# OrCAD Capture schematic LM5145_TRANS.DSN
size E; title: LM5145 6-V to 75-V Synchronous Buck DC-DC Controller; rev: 1.0; note: Datasheet: SNVSAI4     EVM: SNVU545A; note: Synchronous Step Down Converter
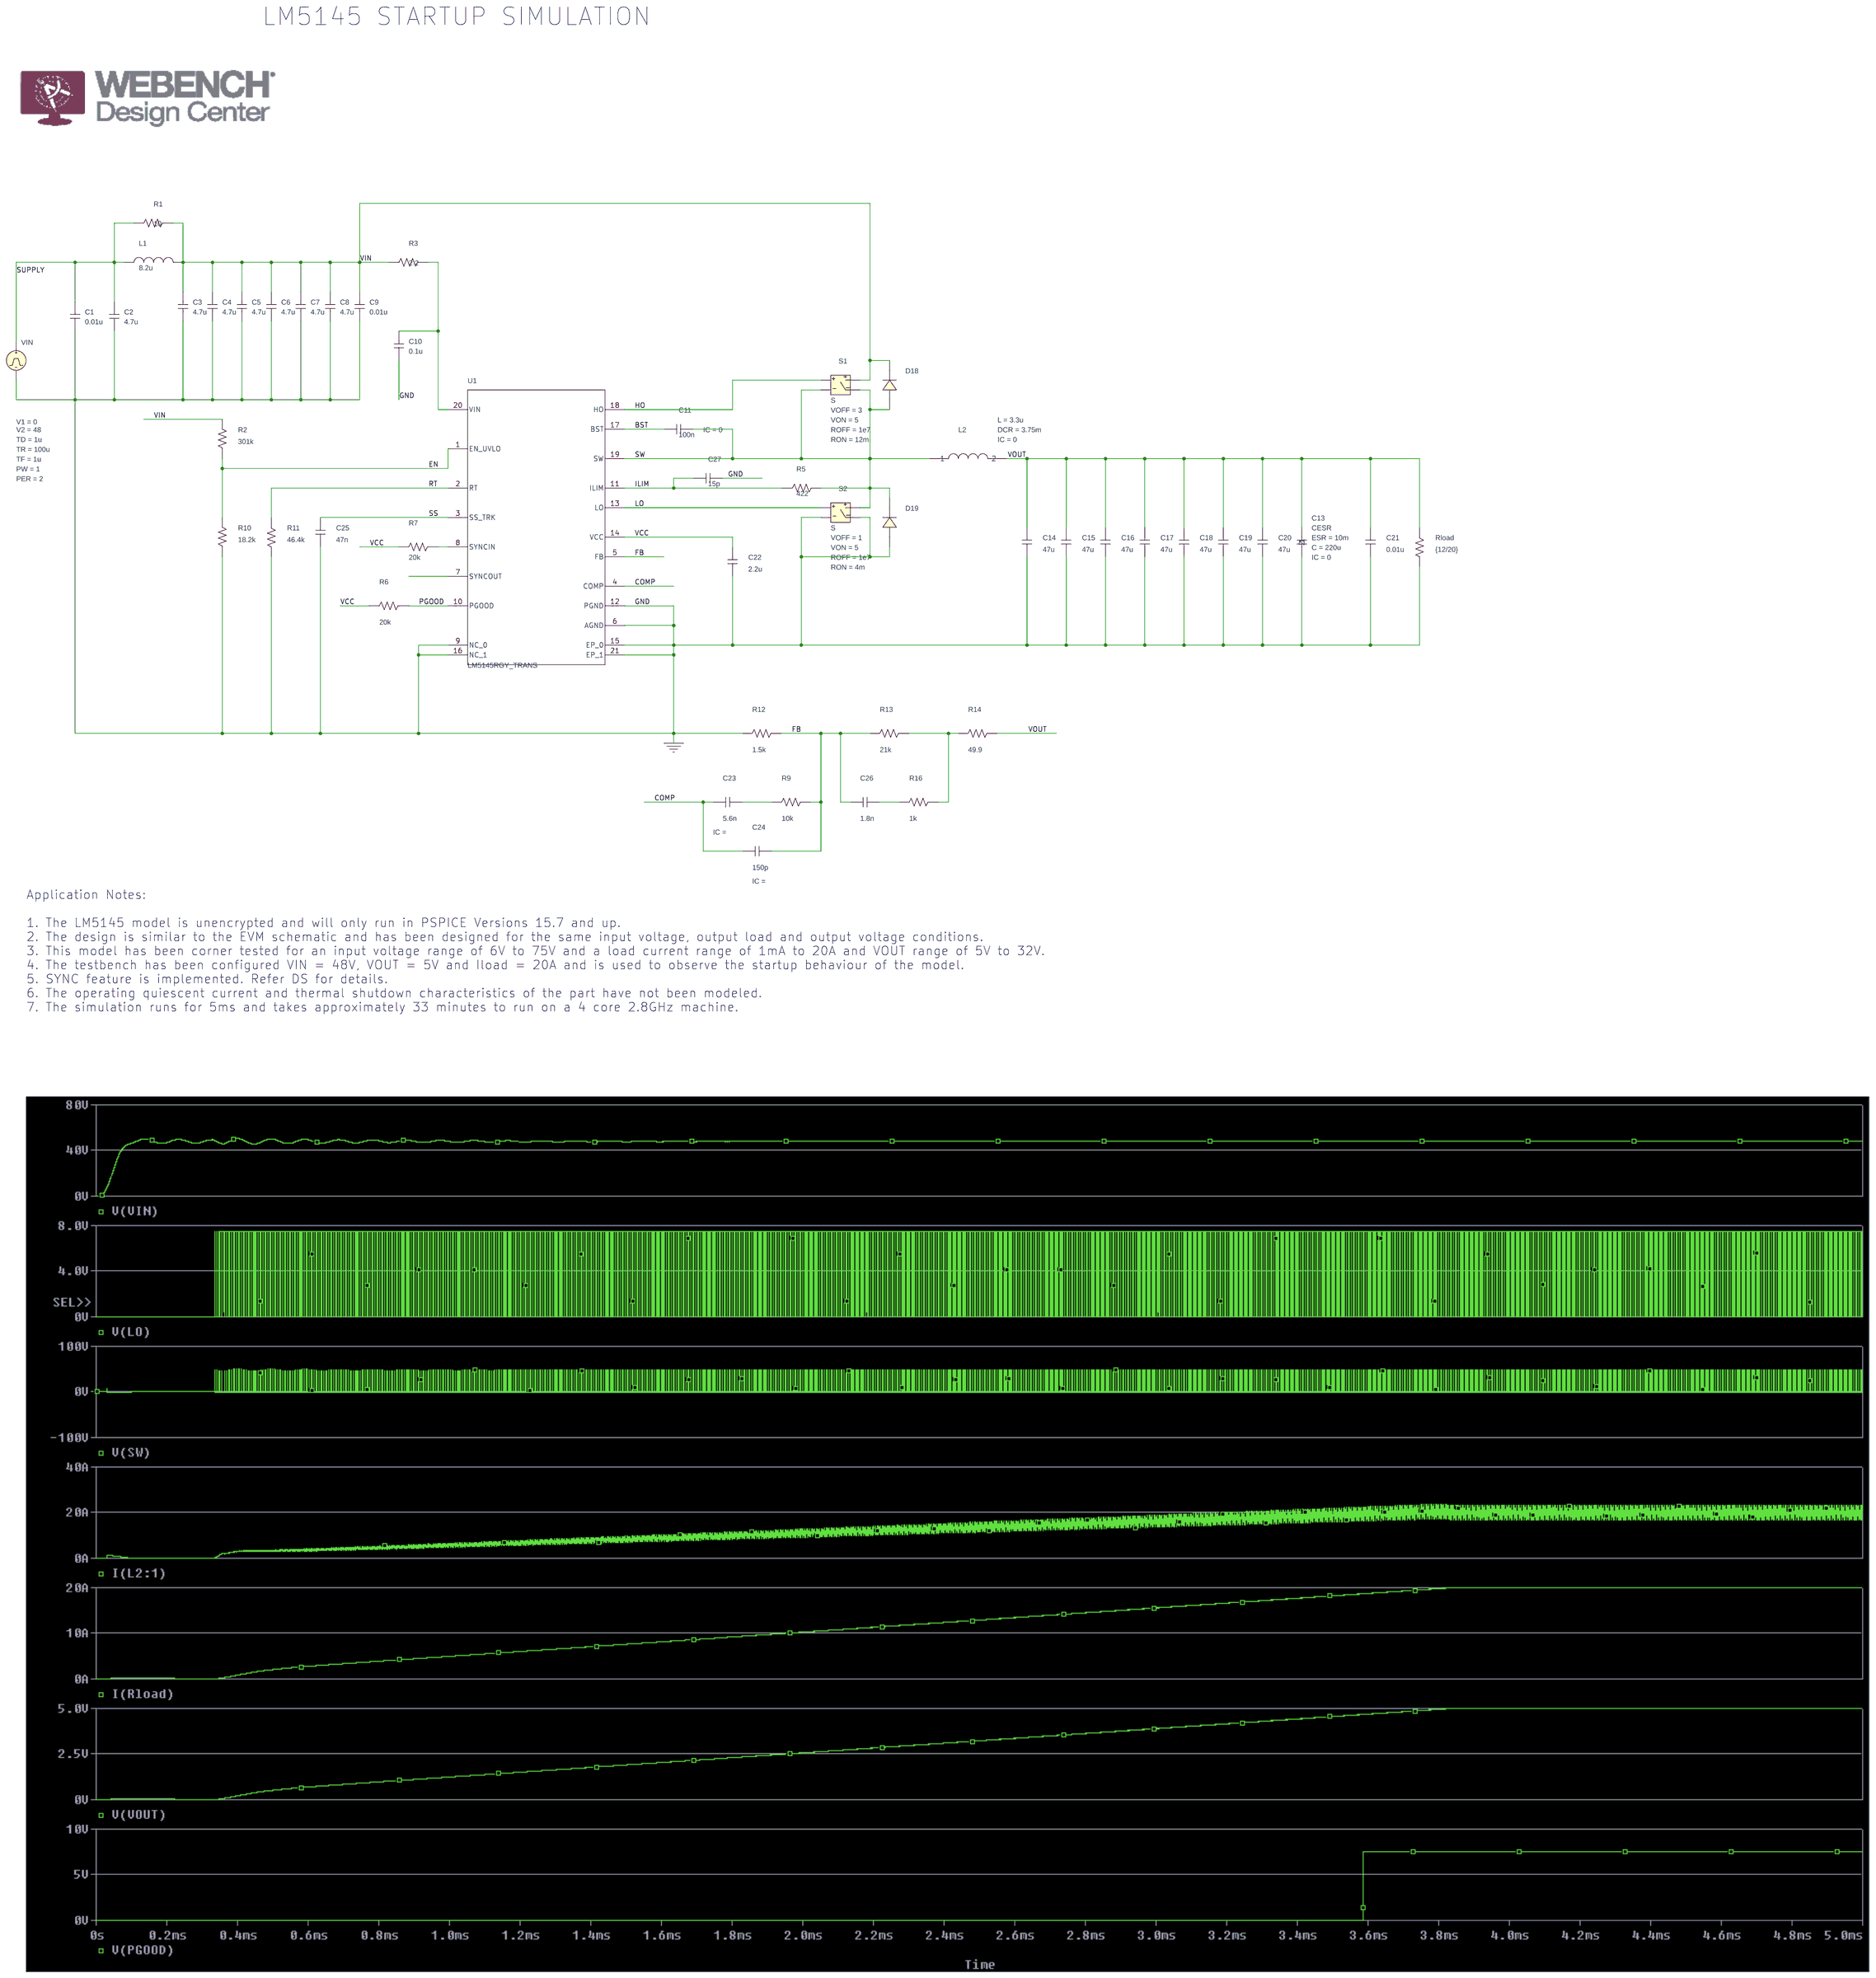
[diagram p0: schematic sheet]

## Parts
C1  0.01u  [RAD/CK05]
C2  4.7u  [RAD/CK05]
C3  4.7u  [RAD/CK05]
C4  4.7u  [RAD/CK05]
C5  4.7u  [RAD/CK05]
C6  4.7u  [RAD/CK05]
C7  4.7u  [RAD/CK05]
C8  4.7u  [RAD/CK05]
C9  0.01u  [RAD/CK05]
C10  0.1u  [RAD/CK05]
C11  100n  [RAD/CK05]
C13  CESR
C14  47u  [RAD/CK05]
C15  47u  [RAD/CK05]
C16  47u  [RAD/CK05]
C17  47u  [RAD/CK05]
C18  47u  [RAD/CK05]
C19  47u  [RAD/CK05]
C20  47u  [RAD/CK05]
C21  0.01u  [RAD/CK05]
C22  2.2u  [RAD/CK05]
C23  5.6n  [RAD/CK05]
C24  150p  [RAD/CK05]
C25  47n  [RAD/CK05]
C26  1.8n  [RAD/CK05]
C27  15p  [RAD/CK05]
D18  D_D1
D19  D_D1
L1  8.2u  [DISC/.350x.175/LS.200x.100/.034]
L2  LDCR
R1  10  [AX/RC05]
R2  301k  [AX/RC05]
R3  2.2  [AX/RC05]
R5  422  [AX/RC05]
R6  20k  [AX/RC05]
R7  20k  [AX/RC05]
R9  10k  [AX/RC05]
R10  18.2k  [AX/RC05]
R11  46.4k  [AX/RC05]
R12  1.5k  [AX/RC05]
R13  21k  [AX/RC05]
R14  49.9  [AX/RC05]
R16  1k  [AX/RC05]
Rload  {12/20}  [AX/RC05]
S1  S
S2  S
U1  LM5145RGY_TRANS  [RGY0020B]
VIN  VPULSE

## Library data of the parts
C1-C10 C14-C27 = c
C11 = c: IC: 0
C13 = CESR: C: 220u; ESR: 10m; IC: 0; PSpiceTemplate: X^@REFDES %1 %2 @MODEL PARAMS: ?C|C=@C||C=10U| ?ESR|ESR=@ESR||ESR=2M| ?IC|IC=@IC||IC=1N| ?X|X=@X||X=1|; X: 1
D18 D19 = D_D1
L1 = l
L2 = LDCR: DCR: 3.75m; IC: 0; L: 3.3u
R1 R3 R5-R7 R9 R11-R14 R16 = r
R2 R10 Rload = R
S1 = S: ROFF: 1e7; RON: 12m; VOFF: 3; VON: 5
S2 = S: ROFF: 1e7; RON: 4m; VOFF: 1; VON: 5
U1 = LM5145RGY_TRANS
VIN = VPULSE: PER: 2; PW: 1; TD: 1u; TF: 1u; TR: 100u; V1: 0; V2: 48

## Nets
VCC: C22.1 R6.2 R7.2 U1.14(VCC)
VIN: C3.1 C4.1 C5.1 C6.1 C7.1 C8.1 C9.1 D18.1(C) L1.2 R1.1 R2.2 R3.2 S1.2(3)
0: C1.2 C2.2 C3.2 C4.2 C5.2 C6.2 C7.2 C8.2 C9.2 C10.2 C13.2 C14.2 C15.2 C16.2 C17.2 C18.2 C19.2 C20.2 C21.2 C22.2 C25.2 C27.2 D19.2(A) R10.1 R11.2 R12.2 Rload.2 S2.1(2) S2.3(4) U1.6(AGND) U1.9(NC_0) U1.12(PGND) U1.15(EP_0) U1.16(NC_1) U1.21(EP_1) VIN.2(-)
BST: C11.1 U1.17(BST)
COMP: C23.2 C24.2 U1.4(COMP)
EN: R2.1 R10.2 U1.1(EN_UVLO)
FB: C24.1 C26.2 R9.1 R12.1 R13.2 U1.5(FB)
HO: S1.0(1) U1.18(HO)
ILIM: C27.1 R5.1 U1.11(ILIM)
LO: S2.0(1) U1.13(LO)
PGOOD: R6.1 U1.10(PGOOD)
RT: R11.1 U1.2(RT)
SS: C25.1 U1.3(SS_TRK)
SUPPLY: C1.1 C2.1 L1.1 R1.2 VIN.1(+)
SW: C11.2 D18.2(A) D19.1(C) L2.1 R5.2 S1.1(2) S1.3(4) S2.2(3) U1.19(SW)
VOUT: C13.1 C14.1 C15.1 C16.1 C17.1 C18.1 C19.1 C20.1 C21.1 L2.2 R14.1 Rload.1
N16860095: R13.1 R14.2 R16.1
N16860193: R7.1 U1.8(SYNCIN)
N16860582: C23.1 R9.2
N16860591: C26.1 R16.2
N16860689: C10.1 R3.1 U1.20(VIN)

Not connected (* = marked no-connect by the designer): U1 7(SYNCOUT)

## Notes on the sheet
- LM5145 STARTUP SIMULATION
- Application Notes:
  1. The LM5145 model is unencrypted and will only run in PSPICE Versions 15.7 and up.
  2. The design is similar to the EVM schematic and has been designed for the same input voltage, output load and output voltage conditions.
  3. This model has been corner tested for an input voltage range of 6V to 75V and a load current range of 1mA to 20A and VOUT range of 5V to 32V.
  4. The testbench has been configured VIN = 48V, VOUT = 5V and Iload = 20A and is used to observe the startup behaviour of the model.
  5. SYNC feature is implemented. Refer DS for details.
  6. The operating quiescent current and thermal shutdown characteristics of the part have not been modeled.
  7. The simulation runs for 5ms and takes approximately 33 minutes to run on a 4 core 2.8GHz machine.
